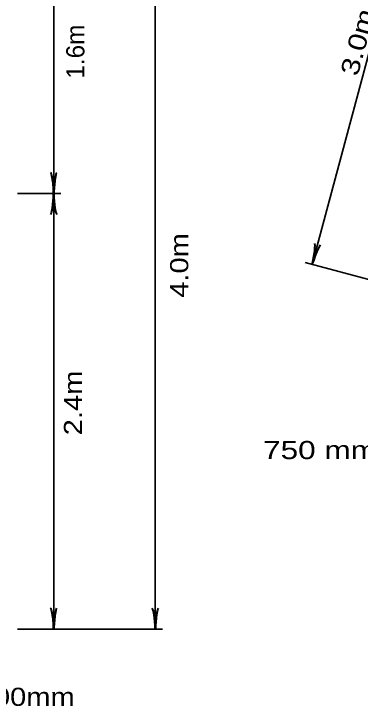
# Model space of a CAD drawing. Extents: x -96 to 617, y -65 to 388.
# Drawn here: x 183.1 to 230.8, y 235 to 330.4 of the extents above; entities that cross this region are included whole.
import ezdxf
from ezdxf.enums import TextEntityAlignment as Align

# ---------------------------------------------------------------- set-up
doc = ezdxf.new("R2010")
doc.units = 0
doc.layers.add('1', color=7, linetype='Continuous', lineweight=53)

msp = doc.modelspace()

# ---------------------------------------------------------------- linework, layer by layer
at = {"layer": '1', "lineweight": 35}
for p, q in [((242.716, 364.843), (224.216, 295.843)), ((188.579, 305.599), (188.579, 345.599)), ((202.579, 345.599), (202.579, 245.599)), ((183.579, 305.599), (189.579, 305.599)), ((188.579, 305.599), (188.579, 245.599)), ((235.352, 292.857), (223.25, 296.102)), ((183.579, 245.599), (203.579, 245.599))]:
    msp.add_line(p, q, dxfattribs=at)
at = {"layer": '1', "lineweight": 40}
for centre, major_axis, ratio, start_param, end_param in [((188.302, 306.69), (0.156, -1.786), 0.122415, 0.896353, 3.141593), ((188.302, 306.69), (0.156, -1.786), 0.122415, 0.896353, 3.141593), ((188.79, 306.719), (-0.176, -1.756), 0.07063, 3.140715, 5.41811), ((188.79, 306.719), (-0.176, -1.756), 0.07063, 3.140715, 5.41811), ((188.367, 304.478), (0.176, 1.756), 0.07063, 3.140715, 5.41811), ((188.367, 304.478), (0.176, 1.756), 0.07063, 3.140715, 5.41811), ((188.855, 304.507), (-0.156, 1.786), 0.122415, 0.896353, 3.141593), ((188.855, 304.507), (-0.156, 1.786), 0.122415, 0.896353, 3.141593), ((224.232, 296.969), (-0.312, -1.765), 0.122415, 0.896353, 3.141593), ((224.711, 296.871), (0.625, 1.651), 0.07063, 6.282307, 8.559703), ((188.302, 246.69), (0.156, -1.786), 0.122415, 0.896353, 3.141593), ((188.302, 246.69), (0.156, -1.786), 0.122415, 0.896353, 3.141593), ((188.79, 246.719), (-0.176, -1.756), 0.07063, 3.140715, 5.41811), ((188.79, 246.719), (-0.176, -1.756), 0.07063, 3.140715, 5.41811), ((202.302, 246.69), (0.156, -1.786), 0.122415, 0.896353, 3.141593), ((202.79, 246.719), (-0.176, -1.756), 0.07063, 3.140715, 5.41811)]:
    msp.add_ellipse(centre, major_axis=major_axis, ratio=ratio, start_param=start_param, end_param=end_param, dxfattribs=at)

# ---------------------------------------------------------------- texts
at = {"layer": '1'}
for s, rotation, width, p in [('3.0m', 74.991, 1.25, (231.684, 326.143)), ('4.0m', 90, 1.2, (207.126, 295.7)), ('2.4m', 90, 1.2, (192.485, 276.758))]:
    msp.add_text(s, height=2.5, rotation=rotation, dxfattribs=dict(at, width=width)).set_placement(p, align=Align.CENTER)
msp.add_text('1.6m', height=2.5, rotation=90, dxfattribs=at).set_placement((192.804, 325.15), align=Align.CENTER)
for s, width, p in [('750 mm', 1.3, (225.294, 269.023)), ('300mm', 1.2, (184.788, 235.031))]:
    msp.add_text(s, height=2.5, dxfattribs=dict(at, width=width)).set_placement(p, align=Align.CENTER)

doc.saveas('drawing.dxf')
